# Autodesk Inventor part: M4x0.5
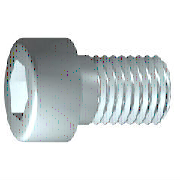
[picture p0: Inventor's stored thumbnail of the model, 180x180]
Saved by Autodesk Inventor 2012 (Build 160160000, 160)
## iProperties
IsCustomPart: 1
Company: 한국ATC센터
Created: 2014-11
Part Number: M4x0.5
Material: 강, 연강
Description: 6각머리 태핑 나사
Document SubType Name: Modeling
Standard: KS B 1003
Designer: KYOUNG IL JANG
Standards Organization: KS
Language: ko-KR
Size Designation: M 4 x 16
Categories: <MemberInstance><Categories><Category DisplayName="조임쇠" InternalName="e4da775c-781d-43d5-af7c-5136215cf5a6" Mnemonic="FSTN"><Category DisplayName="볼트" InternalN
Density: 7.86 g/cm^3
Mass: 2.62973 g
Surface Area: 3.81119 cm^2
Volume: 0.334572 cm^3
Author: KYOUNG IL JANG
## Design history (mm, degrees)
body "Solid1"
workplane "Work Plane1"
fillet "Fillet2" dims "d30" = 0.1 (= R)
revolve "본체" stored, may be unused: angle "d10" = 90 deg
sketch "스케치2"
  geometry: L1 (0, -4.9)-(0, 4.9) reference; L2 (-4.9, 0)-(4.9, 0) reference; L3 (1.732, 0)-(0.866, -1.5); L4 (0.866, -1.5)-(-0.866, -1.5); L5 (-0.866, -1.5)-(-1.732, 0); L6 (-1.732, 0)-(-0.866, 1.5); L7 (-0.866, 1.5)-(0.866, 1.5); L8 (0.866, 1.5)-(1.732, 0); 2 further points
  constraints: 12 end point, 1 coincident, 1 horizontal alignment, 1 point on line, 12 other
extrude "슬롯" join sketch "스케치2" stored distance "d11" = 10; taper "d12" = 0 deg
fillet "모깎기1" dims "d17" = 0.4 (= RR)
feature "스레드" dims "d13" = 14.25 (= GEL), "d14" = 0
chamfer "모따기1" distance "d15" = 0.42941 (= -0.5 x SPD + 0.5 x GD); stored, may be unused: second distance "d16" = 0.42941 (= GUL), angle "d27" = 45 deg
sketch "스케치1"
  geometry: L1 (-1, 0)-(16, 0); L2 (16, 0)-(16, 2); L3 (16, 2)-(1.75, 2); L4 (1.75, 2)-(1.32, 2); L5 (1.32, 2)-(0, 2); L6 (0, 2)-(0, 3.5); L7 (0, 3.5)-(-4, 3.5); L8 (-4, 3.5)-(-4, 1.732); L9 (-4, 1.732)-(-2, 1.732); L10 (-2, 1.732)-(-1, 0); L11 (-8, 0)-(20, 0) reference; L12 (0, -0.7)-(0, 4.2) reference; L13 (1.75, 2)-(0, 2)
  constraints: 22 end point, 6 parallel, 2 collinear, 2 perpendicular, 1 horizontal, 1 point on line
  dimensions: "d1" = 14.25 distance from line of L3.end L2 (= GEL); "d2" = 0.42952 distance of L4.end L3.end (computed from GAL); "d3" = 4 distance between parallel lines of L8 L6 (= KOH); "d4" = 2 distance of L8.end L9.end (= INTI); "d5" = 60 deg angle of L10 L1; "d6" = 4 diameter of L3 L1 (= GD); "d7" = 4 diameter of L5 L1 (= BDM); "d8" = 3.4641 diameter of L9 L1 (= 1.1547 x SW); "d9" = 7 diameter of L7 L1 (= KOD); "d26" = 16 distance between parallel lines of L12 L2 (= NLG)
other parameters: "GD" = 4 (= NND) [user parameter; used in 2 equation terms], "NLG" = 16 [user parameter; used in 1 equation term], "GEL" = 14.25 [user parameter; used in 2 equation terms], "KOD" = 7 [user parameter; used in 1 equation term], "KOH" = 4 [user parameter; used in 1 equation term], "INTI" = 2 [user parameter; used in 1 equation term], "GAL" = 0.42941 (= 0.61345 x PTC) [user parameter; used in 1 equation term], "GUL" = 0.42941 (= 0.61345 x PTC) [user parameter; used in 1 equation term], "BDM" = 4 (= NND) [user parameter; used in 1 equation term], "SW" = 3 [user parameter; used in 2 equation terms], "RR" = 0.4 [user parameter; used in 1 equation term], "SPD" = 3.14117 (= NND - 1.2269 x PTC) [user parameter; used in 1 equation term], "d19" = 0, "d28" = 0, "d29" = 0, "R" = 0.1 [user parameter; used in 1 equation term], "PHH" = 0.2 [user parameter], "GD1" = 3.14117 (= THREADDIA - 1.2269 x PTC) [user parameter], "THREADDIA" = 4 [user parameter; used in 1 equation term], "FAWI" = 45 deg [user parameter], "TPU" = 14.28571 (computed from PTC) [user parameter], "PTC" = 0.7 [user parameter; used in 5 equation terms], "NND" = 4 [user parameter; used in 3 equation terms], "TOA" = 30 deg [user parameter], "E0" = 3.465 (= 1.155 x SW) [user parameter]
